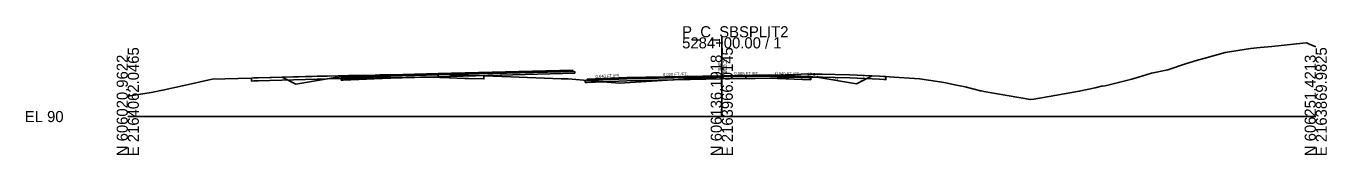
# Model space of a CAD drawing. Extents: x -26 to 1303, y -10 to 12033.
# Drawn here: x -25.7 to 302.8, y 2490.3 to 2522.8 of the extents above; entities that cross this region are included whole.
import ezdxf

# ---------------------------------------------------------------- set-up
doc = ezdxf.new("R2010")
doc.units = 0
for name, color, linetype in [('RD_GPK_XS_Cell', 7, 'Continuous'), ('RD_XS_Base', 7, 'Continuous'), ('RD_XS_ExGround', 7, 'Continuous'), ('RD_XS_ExPaveRet', 7, 'Continuous'), ('RD_XS_Greenside', 7, 'Continuous'), ('RD_XS_Pave', 7, 'Continuous'), ('RD_XS_PaveOvlay_CP', 7, 'Continuous'), ('RD_XS_TieSlope', 7, 'Continuous'), ('RD_XS_TX_Elev_EX', 7, 'Continuous'), ('RD_XS_TX_Elev_PR', 7, 'Continuous'), ('RD_XS_TX_ShdSlope', 7, 'Continuous'), ('RD_XS_TX_Slope', 7, 'Continuous')]:
    doc.layers.add(name, color=color, linetype=linetype)

msp = doc.modelspace()

# ---------------------------------------------------------------- linework, layer by layer
at = {"layer": 'RD_GPK_XS_Cell'}
for p, q in [((150, 2500), (150, 2520)), ((0, 2500), (150, 2500)), ((150, 2500), (300, 2500))]:
    msp.add_line(p, q, dxfattribs=at)
at = {"layer": 'RD_XS_Base'}
for p, q in [((66.16, 2510.19), (54.41, 2509.72)), ((66.42, 2510.2), (66.16, 2510.19)), ((78.41, 2510.51), (66.42, 2510.2)), ((66.42, 2509.7), (78.41, 2510.01)), ((78.41, 2510.51), (112.91, 2511.41)), ((112.91, 2510.91), (78.41, 2510.01)), ((78.41, 2510.01), (78.41, 2510.67)), ((78.41, 2510.67), (78.41, 2510.67)), ((78.41, 2510.67), (78.41, 2510.67)), ((78.41, 2510.67), (78.41, 2510.51)), ((78.41, 2510.51), (78.41, 2510.51)), ((78.41, 2510.01), (78.41, 2510.51)), ((78.41, 2510.51), (78.41, 2510.51)), ((78.41, 2510.51), (78.41, 2510.51)), ((78.41, 2510.01), (78.41, 2510.01)), ((102.41, 2511.13), (102.41, 2511.13)), ((102.41, 2511.13), (102.41, 2511.13)), ((102.41, 2510.63), (102.41, 2510.63)), ((102.41, 2510.63), (102.41, 2510.63)), ((112.41, 2511.39), (112.41, 2511.39)), ((112.91, 2511.41), (112.91, 2510.91)), ((112.91, 2511.37), (112.91, 2511.37)), ((150, 2510), (126, 2509.52)), ((150, 2510), (162, 2510.17)), ((150, 2509.5), (150, 2510.16)), ((150, 2510.16), (150, 2510.16)), ((150, 2510.16), (150, 2510.16)), ((150, 2510.16), (150, 2510)), ((150, 2510), (150, 2510)), ((150, 2509.5), (150, 2510)), ((150, 2510), (150, 2510)), ((150, 2510), (150, 2510)), ((162, 2510.17), (162, 2510.17)), ((162, 2510.17), (162, 2510.17)), ((162, 2510.17), (172, 2509.77)), ((54.39, 2509.72), (53.91, 2509.7)), ((53.91, 2509.7), (53.91, 2509.68)), ((53.91, 2509.68), (53.91, 2509.2)), ((53.91, 2509.2), (54.39, 2509.22)), ((54.41, 2509.72), (54.39, 2509.72)), ((54.39, 2509.22), (54.41, 2509.22)), ((54.41, 2509.22), (66.16, 2509.69)), ((66.16, 2509.69), (66.42, 2509.7)), ((116, 2509.12), (115.5, 2509.1)), ((115.5, 2509.1), (115.5, 2509.1)), ((115.5, 2509.1), (115.5, 2508.6)), ((115.5, 2508.6), (116, 2508.62)), ((126, 2509.52), (116, 2509.12)), ((116, 2509.12), (116, 2509.12)), ((116, 2508.62), (126, 2509.02)), ((116, 2508.62), (116, 2508.62)), ((126, 2509.52), (126, 2509.52)), ((126, 2509.02), (150, 2509.5)), ((126, 2509.02), (126, 2509.02)), ((162, 2509.67), (150, 2509.5)), ((150, 2509.5), (150, 2509.5)), ((172.5, 2509.25), (162, 2509.67)), ((162, 2509.67), (162, 2509.67)), ((162, 2509.67), (162, 2509.67)), ((172, 2509.77), (172, 2509.77)), ((172, 2509.77), (172.5, 2509.75)), ((172.5, 2509.75), (172.5, 2509.75)), ((172.5, 2509.75), (172.5, 2509.25))]:
    msp.add_line(p, q, dxfattribs=at)
at = {"layer": 'RD_XS_ExGround'}
msp.add_lwpolyline([(0, 2505.17), (5.94, 2506.07), (9.22, 2506.72), (13.82, 2507.77), (21.3, 2509.41), (27.89, 2509.6), (31.25, 2509.72), (32.93, 2509.76), (49.95, 2510.22), (50.43, 2510.23), (55.95, 2510.35), (63.06, 2510.47), (63.66, 2510.49), (66.01, 2510.5), (66.16, 2510.5), (66.25, 2510.5), (66.26, 2510.5), (73.99, 2510.71), (74.36, 2510.71), (75.72, 2510.67), (79.16, 2510.63), (85.12, 2510.39), (89.94, 2510.26), (96.75, 2510.03), (109.42, 2509.56), (111.21, 2509.49), (118.97, 2508.83), (124.18, 2508.42), (140.32, 2509.47), (140.85, 2509.5), (141.66, 2509.55), (146.44, 2509.76), (156.07, 2510.33), (158.44, 2510.38), (166.17, 2510.55), (166.92, 2510.57), (171.64, 2510.75), (171.84, 2510.69), (173.92, 2510.72), (175.38, 2510.69), (178.64, 2510.62), (182.33, 2510.5), (189.84, 2510.15), (190.93, 2510.1), (191.46, 2510.07), (192.26, 2510.02), (199.94, 2509.5), (205.1, 2508.74), (206.55, 2508.53), (208.46, 2508.12), (211.43, 2507.5), (215.31, 2506.53), (215.53, 2506.48), (216.16, 2506.36), (227.93, 2504.28), (228.83, 2504.4), (234.09, 2505.32), (240.3, 2506.38), (244.33, 2507.24), (245.94, 2507.64), (246.11, 2507.64), (246.79, 2507.79), (253.57, 2509.41), (254.87, 2509.86), (255.27, 2509.97), (258.51, 2510.92), (262.61, 2511.78), (267.13, 2513.28), (270.18, 2514.21), (271.73, 2514.63), (277.14, 2516.13), (283.49, 2517.18), (285.93, 2517.39), (288.95, 2517.72), (296.7, 2518.54), (297.64, 2518.63), (297.89, 2518.52), (298.04, 2518.44), (300, 2517.56)], dxfattribs=at)
at = {"layer": 'RD_XS_ExPaveRet'}
for points in [[(89.94, 2510.26), (86.04, 2510.37), (85.12, 2510.39), (79.21, 2510.63), (79.16, 2510.63), (79.14, 2510.63), (78.83, 2510.63), (75.79, 2510.67), (75.73, 2510.67), (74.37, 2510.71), (74.36, 2510.71), (74.36, 2510.71), (73.99, 2510.71), (73.98, 2510.71), (73.97, 2510.71), (73.94, 2510.71), (66.64, 2510.51), (66.19, 2510.5), (66.05, 2510.5), (63.76, 2510.49), (63.7, 2510.49), (62.82, 2510.47), (62.46, 2510.46), (56.27, 2510.36), (55.95, 2510.35), (55.72, 2510.35), (50.44, 2510.23), (49.95, 2510.22), (49.94, 2510.22), (49.81, 2510.21), (47.84, 2510.16), (32.93, 2509.76), (31.85, 2509.73), (31.25, 2509.72), (31.25, 2509.55), (31.25, 2508.97), (31.85, 2508.98), (32.93, 2509.01), (47.84, 2509.41), (49.81, 2509.46), (49.94, 2509.47), (49.95, 2509.47), (50.44, 2509.48), (55.72, 2509.6), (55.95, 2509.6), (56.27, 2509.61), (62.46, 2509.71), (62.82, 2509.72), (63.7, 2509.74), (63.76, 2509.74), (66.05, 2509.75), (66.19, 2509.75), (66.64, 2509.76), (73.94, 2509.96), (73.97, 2509.96), (73.98, 2509.96), (73.99, 2509.96), (74.36, 2509.96), (74.36, 2509.96), (74.37, 2509.96), (75.73, 2509.92), (75.79, 2509.92), (78.83, 2509.88), (79.14, 2509.88), (79.16, 2509.88), (79.21, 2509.88), (85.12, 2509.64), (86.04, 2509.62), (89.94, 2509.51), (89.94, 2509.51), (89.94, 2509.51), (89.94, 2509.72), (89.94, 2510.26), (89.94, 2510.26), (89.94, 2510.26)], [(89.94, 2510.26), (86.04, 2510.37), (85.12, 2510.39), (79.21, 2510.63), (79.16, 2510.63), (79.14, 2510.63), (78.83, 2510.63), (75.79, 2510.67), (75.73, 2510.67), (74.37, 2510.71), (74.36, 2510.71), (74.36, 2510.71), (73.99, 2510.71), (73.98, 2510.71), (73.97, 2510.71), (73.94, 2510.71), (66.64, 2510.51), (66.19, 2510.5), (66.05, 2510.5), (63.76, 2510.49), (63.7, 2510.49), (62.82, 2510.47), (62.46, 2510.46), (56.27, 2510.36), (55.95, 2510.35), (55.72, 2510.35), (50.44, 2510.23), (49.95, 2510.22), (49.94, 2510.22), (49.81, 2510.21), (47.84, 2510.16), (32.93, 2509.76), (31.85, 2509.73), (31.25, 2509.72), (31.25, 2509.55), (31.25, 2508.97), (31.85, 2508.98), (32.93, 2509.01), (47.84, 2509.41), (49.81, 2509.46), (49.94, 2509.47), (49.95, 2509.47), (50.44, 2509.48), (55.72, 2509.6), (55.95, 2509.6), (56.27, 2509.61), (62.46, 2509.71), (62.82, 2509.72), (63.7, 2509.74), (63.76, 2509.74), (66.05, 2509.75), (66.19, 2509.75), (66.64, 2509.76), (73.94, 2509.96), (73.97, 2509.96), (73.98, 2509.96), (73.99, 2509.96), (74.36, 2509.96), (74.36, 2509.96), (74.37, 2509.96), (75.73, 2509.92), (75.79, 2509.92), (78.83, 2509.88), (79.14, 2509.88), (79.16, 2509.88), (79.21, 2509.88), (85.12, 2509.64), (86.04, 2509.62), (89.94, 2509.51), (89.94, 2509.72), (89.94, 2510.26)], [(191.46, 2510.07), (191.46, 2510.07), (191.46, 2509.32), (190.93, 2509.35), (189.84, 2509.4), (189.84, 2509.4), (182.33, 2509.75), (178.64, 2509.87), (178.64, 2509.87), (175.38, 2509.94), (175.38, 2509.94), (173.92, 2509.97), (173.92, 2509.97), (173.92, 2509.97), (171.84, 2509.94), (171.64, 2510), (171.64, 2510), (171.64, 2510), (166.92, 2509.82), (166.92, 2509.82), (166.17, 2509.8), (166.17, 2509.8), (158.44, 2509.63), (158.44, 2509.63), (156.07, 2509.58), (156.07, 2509.58), (156.07, 2510.33), (156.07, 2510.33), (156.07, 2510.33), (158.44, 2510.38), (158.44, 2510.38), (166.17, 2510.55), (166.17, 2510.55), (166.92, 2510.57), (166.92, 2510.57), (171.64, 2510.75), (171.64, 2510.75), (171.64, 2510.75), (171.84, 2510.69), (173.92, 2510.72), (173.92, 2510.72), (173.92, 2510.72), (175.38, 2510.69), (175.38, 2510.69), (178.64, 2510.62), (178.64, 2510.62), (182.33, 2510.5), (189.84, 2510.15), (189.84, 2510.15), (190.93, 2510.1), (191.46, 2510.07)], [(190.93, 2510.1), (189.84, 2510.15), (182.33, 2510.5), (178.64, 2510.62), (175.38, 2510.69), (173.92, 2510.72), (171.84, 2510.69), (171.64, 2510.75), (166.92, 2510.57), (166.17, 2510.55), (158.44, 2510.38), (156.07, 2510.33), (156.07, 2510.33), (156.07, 2509.58), (156.07, 2509.58), (158.44, 2509.63), (166.17, 2509.8), (166.92, 2509.82), (171.64, 2510), (171.84, 2509.94), (173.92, 2509.97), (175.38, 2509.94), (178.64, 2509.87), (182.33, 2509.75), (189.84, 2509.4), (190.93, 2509.35), (191.46, 2509.32), (191.46, 2510.07), (190.93, 2510.1)]]:
    msp.add_lwpolyline(points, dxfattribs=at)
at = {"layer": 'RD_XS_Greenside'}
for p, q in [((184, 2508.26), (187.96, 2510.24)), ((42.41, 2508.21), (38.99, 2509.92)), ((52.41, 2509.88), (42.41, 2508.21)), ((174, 2509.93), (184, 2508.26))]:
    msp.add_line(p, q, dxfattribs=at)
at = {"layer": 'RD_XS_Pave'}
for p, q in [((54.41, 2510.04), (66.16, 2510.51)), ((66.16, 2510.35), (54.41, 2509.88)), ((66.16, 2510.35), (54.41, 2509.88)), ((54.41, 2509.72), (66.16, 2510.19)), ((54.41, 2510.03), (54.41, 2510.04)), ((54.41, 2509.88), (54.41, 2510.03)), ((66.16, 2510.51), (66.42, 2510.52)), ((66.42, 2510.36), (66.16, 2510.35)), ((66.42, 2510.36), (66.16, 2510.35)), ((66.16, 2510.19), (66.42, 2510.2)), ((66.42, 2510.52), (78.41, 2510.83)), ((78.41, 2510.67), (66.42, 2510.36)), ((78.41, 2510.67), (66.42, 2510.36)), ((66.42, 2510.2), (78.41, 2510.51)), ((112.41, 2511.71), (78.41, 2510.83)), ((112.41, 2511.55), (78.41, 2510.67)), ((78.41, 2510.67), (112.41, 2511.55)), ((78.41, 2510.51), (112.41, 2511.39)), ((78.41, 2510.83), (78.41, 2510.83)), ((78.41, 2510.67), (78.41, 2510.67)), ((78.41, 2510.67), (78.41, 2510.67)), ((78.41, 2510.67), (78.41, 2510.51)), ((78.41, 2510.67), (78.41, 2510.67)), ((78.41, 2510.51), (78.41, 2510.67)), ((78.41, 2510.67), (78.41, 2510.67)), ((78.41, 2510.67), (78.41, 2510.67)), ((78.41, 2510.51), (78.41, 2510.51)), ((78.41, 2510.51), (78.41, 2510.51)), ((102.41, 2511.45), (102.41, 2511.45)), ((102.41, 2511.45), (102.41, 2511.45)), ((102.41, 2511.29), (102.41, 2511.29)), ((102.41, 2511.29), (102.41, 2511.29)), ((102.41, 2511.29), (102.41, 2511.29)), ((102.41, 2511.29), (102.41, 2511.29)), ((102.41, 2511.13), (102.41, 2511.13)), ((102.41, 2511.13), (102.41, 2511.13)), ((112.41, 2511.55), (112.41, 2511.71)), ((112.41, 2511.71), (112.41, 2511.71)), ((112.41, 2511.39), (112.41, 2511.55)), ((112.41, 2511.55), (112.41, 2511.55)), ((150, 2510.31), (126, 2509.83)), ((150, 2510.16), (126, 2509.68)), ((126, 2509.68), (150, 2510.16)), ((126, 2509.52), (150, 2510)), ((162, 2510.49), (150, 2510.31)), ((162, 2510.33), (150, 2510.16)), ((150, 2510.16), (162, 2510.33)), ((150, 2510.31), (150, 2510.31)), ((150, 2510), (162, 2510.17)), ((150, 2510), (150, 2510.16)), ((150, 2510.16), (150, 2510.16)), ((150, 2510.16), (150, 2510.16)), ((150, 2510.16), (150, 2510.16)), ((150, 2510.16), (150, 2510.16)), ((150, 2510.16), (150, 2510)), ((150, 2510.16), (150, 2510.16)), ((150, 2510), (150, 2510)), ((150, 2510), (150, 2510)), ((172, 2510.09), (162, 2510.49)), ((162, 2510.49), (162, 2510.49)), ((162, 2510.49), (162, 2510.49)), ((172, 2509.93), (162, 2510.33)), ((162, 2510.33), (162, 2510.33)), ((162, 2510.33), (162, 2510.33)), ((162, 2510.33), (162, 2510.33)), ((162, 2510.33), (162, 2510.33)), ((162, 2510.33), (172, 2509.93)), ((162, 2510.17), (172, 2509.77)), ((162, 2510.17), (162, 2510.17)), ((162, 2510.17), (162, 2510.17)), ((172, 2509.93), (172, 2510.09)), ((172, 2510.09), (172, 2510.09)), ((54.41, 2509.88), (54.41, 2509.87)), ((54.41, 2509.87), (54.41, 2509.72)), ((126, 2509.83), (116, 2509.43)), ((126, 2509.68), (116, 2509.28)), ((116, 2509.28), (126, 2509.68)), ((116, 2509.12), (126, 2509.52)), ((116, 2509.43), (116, 2509.43)), ((116, 2509.43), (116, 2509.28)), ((116, 2509.28), (116, 2509.28)), ((116, 2509.28), (116, 2509.12)), ((126, 2509.83), (126, 2509.83)), ((126, 2509.68), (126, 2509.68)), ((126, 2509.68), (126, 2509.68)), ((126, 2509.52), (126, 2509.52)), ((172, 2509.77), (172, 2509.93)), ((172, 2509.93), (172, 2509.93))]:
    msp.add_line(p, q, dxfattribs=at)
at = {"layer": 'RD_XS_PaveOvlay_CP'}
for p, q in [((54.41, 2510.04), (66.16, 2510.51)), ((66.16, 2510.51), (66.42, 2510.52)), ((66.42, 2510.52), (78.41, 2510.83)), ((112.41, 2511.71), (78.41, 2510.83)), ((78.41, 2510.83), (78.41, 2510.83)), ((102.41, 2511.45), (102.41, 2511.45)), ((102.41, 2511.45), (102.41, 2511.45)), ((150, 2510.31), (126, 2509.83)), ((162, 2510.49), (150, 2510.31)), ((150, 2510.31), (150, 2510.31)), ((172, 2510.09), (162, 2510.49)), ((162, 2510.49), (162, 2510.49)), ((162, 2510.49), (162, 2510.49)), ((126, 2509.83), (116, 2509.43)), ((126, 2509.83), (126, 2509.83))]:
    msp.add_line(p, q, dxfattribs=at)
at = {"layer": 'RD_XS_TieSlope'}
for p, q in [((54.41, 2510.04), (52.41, 2509.88)), ((172, 2510.09), (174, 2509.93))]:
    msp.add_line(p, q, dxfattribs=at)

# ---------------------------------------------------------------- texts
at = {"layer": 'RD_GPK_XS_Cell'}
for s, p in [('5284+00.00 / 1', (140, 2517.2)), ('P_C_SBSPLIT2', (140, 2520)), ('EL 90', (-26, 2498.6))]:
    msp.add_text(s, height=2.8, dxfattribs=at).set_placement(p)
for s, p in [('E 2164062.0465', (2.8, 2490)), ('E 2163966.0145', (152.8, 2490)), ('E 2163869.9825', (302.8, 2490)), ('N 606020.9622', (0, 2490)), ('N 606136.1918', (150, 2490)), ('N 606251.4213', (300, 2490))]:
    msp.add_text(s, height=2.8, rotation=90, dxfattribs=at).set_placement(p)
at = {"layer": 'RD_XS_TX_Elev_EX'}
msp.add_text('99.98', height=0.6, rotation=90, dxfattribs=at).set_placement((149.65, 2511.41))
at = {"layer": 'RD_XS_TX_Elev_PR'}
msp.add_text('100.31', height=1, rotation=90, dxfattribs=at).set_placement((151.35, 2510.85))
at = {"layer": 'RD_XS_TX_ShdSlope'}
msp.add_text('12.5:1', height=0.75, rotation=355.4261, dxfattribs=at).set_placement((171.56, 2510.38))
at = {"layer": 'RD_XS_TX_Slope'}
for s, rotation, p in [('0.040 FT./FT.', 2.2906, (118.15, 2509.73)), ('0.020 FT./FT.', 1.1458, (135.16, 2510.22)), ('0.005 FT./FT.', 359.6977, (153.16, 2510.5)), ('0.040 FT./FT.', 357.7094, (163.51, 2510.54)), ('6:1', 350.5358, (178.13, 2509.39)), ('2:1', 26.5651, (185.08, 2508.99))]:
    msp.add_text(s, height=0.75, rotation=rotation, dxfattribs=at).set_placement(p)

doc.saveas('drawing.dxf')
